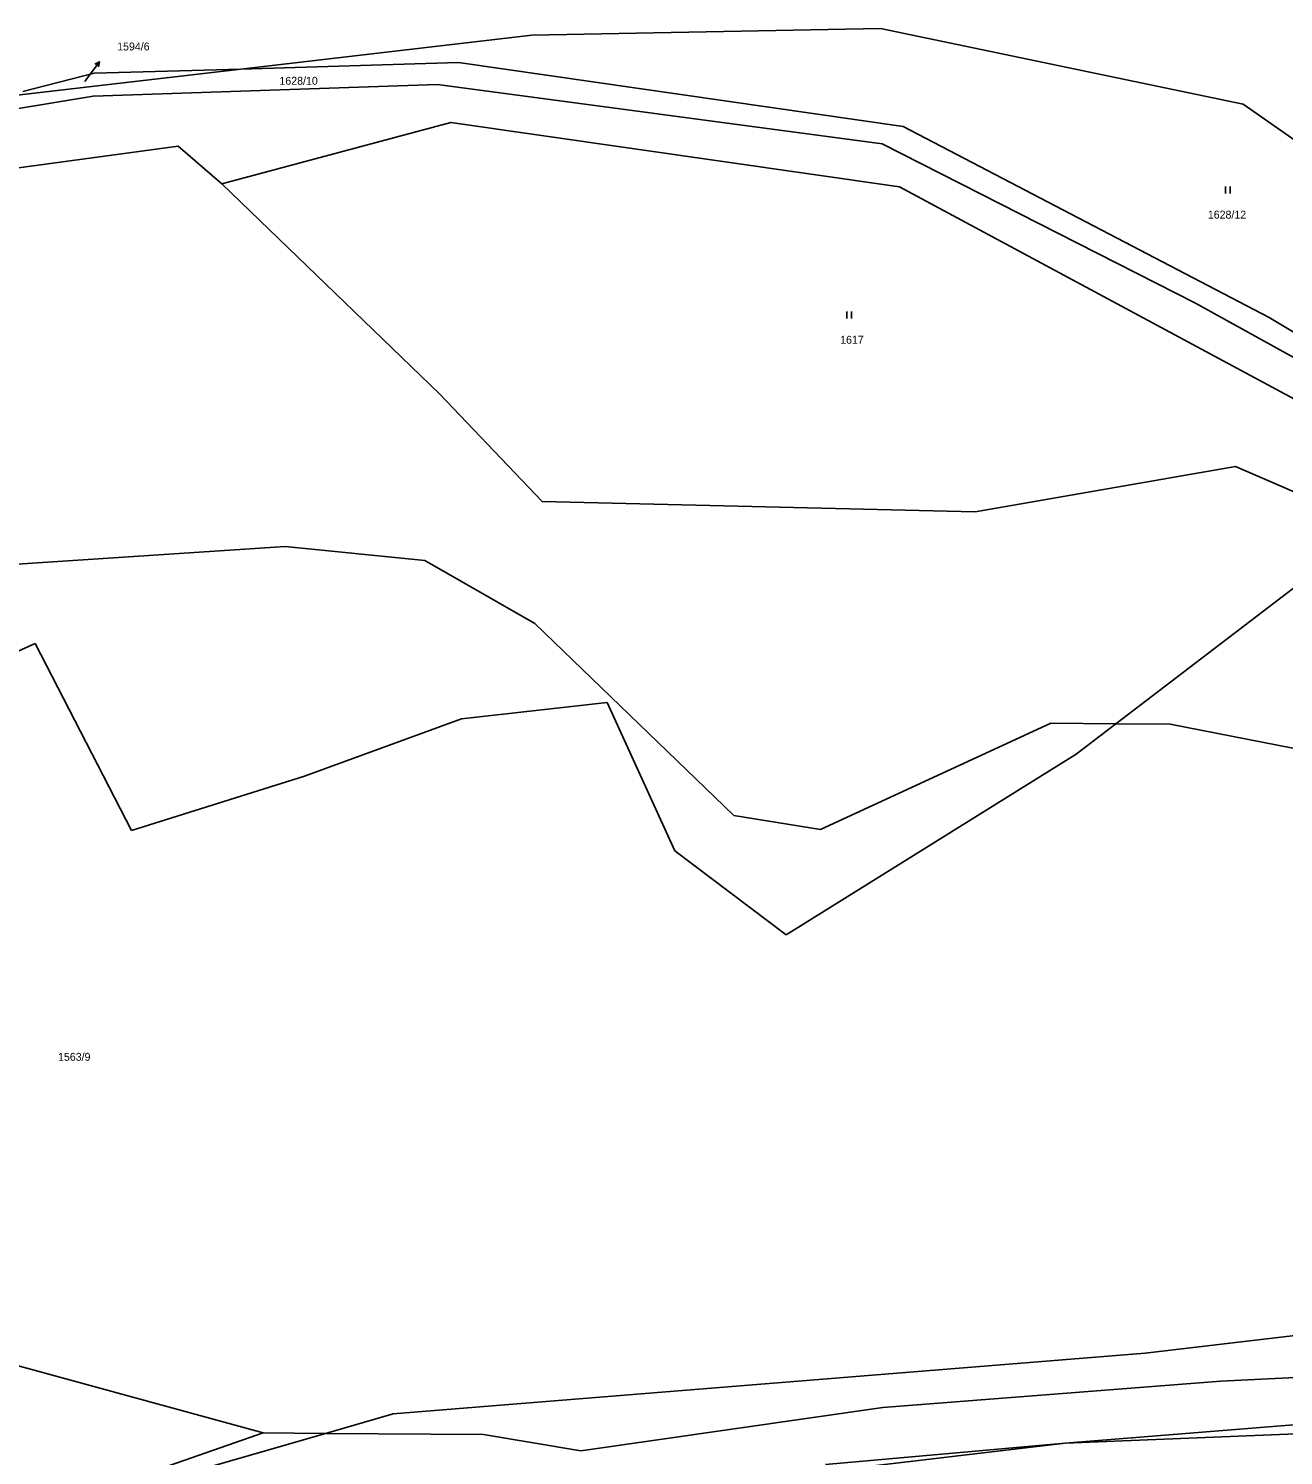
# Model space of a CAD drawing. Extents: x -747792 to -745414, y -1093712 to -1091463.
# Drawn here: x -747344.5 to -747209.9, y -1092152.8 to -1091999.7 of the extents above; entities that cross this region are included whole.
import ezdxf

# ---------------------------------------------------------------- set-up
doc = ezdxf.new("R2010")
doc.units = 0
for name, color, linetype in [('Pracovní_bod JDTM STC_VC', 7, 'Continuous'), ('Pracovní_bod JDTM STC_VC - číslo', 7, 'Continuous'), ('Pracovní_bod NN - výška', 7, 'Continuous'), ('Pracovní_bod polohopisu - výška', 7, 'Continuous')]:
    doc.layers.add(name, color=color, linetype=linetype)

msp = doc.modelspace()

# ---------------------------------------------------------------- linework, layer by layer
at = {"layer": 'Pracovní_bod JDTM STC_VC - číslo'}
for points in [[(-747216.16, -1092016.67), (-747216.16, -1092017.42)], [(-747215.66, -1092017.42), (-747215.66, -1092016.67)], [(-747256.78, -1092030.09), (-747256.78, -1092030.84)], [(-747256.28, -1092030.84), (-747256.28, -1092030.09)]]:
    msp.add_lwpolyline(points, dxfattribs=at)
at = {"layer": 'Pracovní_bod NN - výška'}
for points in [[(-747290.56, -1092000.45), (-747253.15, -1091999.74)], [(-747253.15, -1091999.74), (-747214.27, -1092007.85)], [(-747321.75, -1092004.08), (-747290.56, -1092000.45)], [(-747298.42, -1092003.39), (-747321.75, -1092004.08)], [(-747250.71, -1092010.26), (-747298.42, -1092003.39)], [(-747354.38, -1092007.87), (-747321.75, -1092004.08)], [(-747337.47, -1092004.54), (-747345.13, -1092006.48)], [(-747321.75, -1092004.08), (-747337.47, -1092004.54)], [(-747337.6, -1092007), (-747300.66, -1092005.74)], [(-747300.66, -1092005.74), (-747252.97, -1092012.12)], [(-747375.49, -1092013.26), (-747337.6, -1092007)], [(-747214.27, -1092007.85), (-747203.47, -1092015.38)], [(-747323.79, -1092016.4), (-747299.22, -1092009.8)], [(-747299.22, -1092009.8), (-747251.1, -1092016.73)], [(-747211.48, -1092030.71), (-747250.71, -1092010.26)], [(-747328.46, -1092012.34), (-747378.3, -1092019.1)], [(-747323.79, -1092016.4), (-747328.46, -1092012.34)], [(-747219.39, -1092029.19), (-747252.97, -1092012.12)], [(-747300.44, -1092038.9), (-747323.79, -1092016.4)], [(-747251.1, -1092016.73), (-747208.29, -1092039.75)], [(-747207.3, -1092035.89), (-747219.39, -1092029.19)], [(-747205.49, -1092034.31), (-747211.48, -1092030.71)], [(-747289.42, -1092050.47), (-747300.44, -1092038.9)], [(-747215.07, -1092046.72), (-747242.99, -1092051.55)], [(-747200.22, -1092053.14), (-747215.07, -1092046.72)], [(-747242.99, -1092051.55), (-747289.42, -1092050.47)], [(-747316.98, -1092055.28), (-747357.66, -1092057.98)], [(-747302.02, -1092056.79), (-747316.98, -1092055.28)], [(-747202.36, -1092054.78), (-747227.92, -1092074.29)], [(-747290.22, -1092063.54), (-747302.02, -1092056.79)], [(-747268.89, -1092084.12), (-747290.22, -1092063.54)], [(-747343.8, -1092065.69), (-747381.51, -1092082.64)], [(-747333.47, -1092085.74), (-747343.8, -1092065.69)], [(-747282.48, -1092072.01), (-747298.08, -1092073.75)], [(-747275.19, -1092087.91), (-747282.48, -1092072.01)], [(-747298.08, -1092073.75), (-747314.91, -1092079.92)], [(-747234.9, -1092074.22), (-747259.59, -1092085.63)], [(-747227.92, -1092074.29), (-747234.9, -1092074.22)], [(-747227.92, -1092074.29), (-747232.18, -1092077.54)], [(-747222.08, -1092074.35), (-747227.92, -1092074.29)], [(-747195.96, -1092079.44), (-747222.08, -1092074.35)], [(-747232.18, -1092077.54), (-747263.28, -1092096.94)], [(-747314.91, -1092079.92), (-747333.47, -1092085.74)], [(-747259.59, -1092085.63), (-747268.89, -1092084.12)], [(-747263.28, -1092096.94), (-747275.19, -1092087.91)], [(-747411.23, -1092125.19), (-747319.36, -1092150.34)], [(-747208.4, -1092139.84), (-747224.76, -1092141.77)], [(-747224.76, -1092141.77), (-747305.43, -1092148.3)], [(-747194.11, -1092143.68), (-747216.67, -1092144.8)], [(-747216.67, -1092144.8), (-747252.89, -1092147.61)], [(-747305.43, -1092148.3), (-747312.67, -1092150.39)], [(-747252.89, -1092147.61), (-747285.3, -1092152.24)], [(-747193.27, -1092148.22), (-747233.36, -1092151.44)], [(-747319.36, -1092150.34), (-747341.6, -1092158.07)], [(-747312.67, -1092150.39), (-747319.36, -1092150.34)], [(-747203.28, -1092150.22), (-747233.36, -1092151.44)], [(-747312.67, -1092150.39), (-747333.27, -1092156.33)], [(-747295.73, -1092150.51), (-747312.67, -1092150.39)], [(-747285.3, -1092152.24), (-747295.73, -1092150.51)], [(-747279.94, -1092156.93), (-747233.36, -1092151.44)], [(-747233.36, -1092151.44), (-747259.05, -1092153.71)]]:
    msp.add_lwpolyline(points, dxfattribs=at)
at = {"layer": 'Pracovní_bod polohopisu - výška'}
for points in [[(-747336.91, -1092003.3), (-747337.8, -1092004.5)], [(-747337.4, -1092003.55), (-747336.91, -1092003.3), (-747337, -1092003.85)], [(-747338.49, -1092005.43), (-747337.8, -1092004.5)]]:
    msp.add_lwpolyline(points, dxfattribs=at)

# ---------------------------------------------------------------- texts
at = {"layer": 'Pracovní_bod JDTM STC_VC'}
for s, height, p in [('1628/10', 0.85, (-747317.61, -1092005.77)), ('1594/6', 0.05, (-747338.6, -1092005.43)), ('1628/12', 0.85, (-747218.05, -1092020.12)), ('1617', 0.85, (-747257.48, -1092033.54)), ('1563/9', 0.85, (-747341.35, -1092110.43))]:
    msp.add_text(s, height=height, dxfattribs=at).set_placement(p)
at = {"layer": 'Pracovní_bod polohopisu - výška'}
msp.add_text('1594/6', height=0.85, dxfattribs=at).set_placement((-747335.01, -1092002.09))

doc.saveas('drawing.dxf')
